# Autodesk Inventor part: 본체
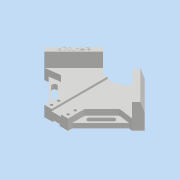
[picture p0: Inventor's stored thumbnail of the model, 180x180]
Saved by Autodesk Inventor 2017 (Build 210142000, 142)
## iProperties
Part Number: 본체
Material: 일반
Document SubType Name: Modeling
Designer: mrc
Density: 1 g/cm^3
Appearance: 기본값
Mass: 211.713 g
Surface Area: 407.173 cm^2
Volume: 211.713 cm^3
Author: mrc
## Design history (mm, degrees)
node "스케치1"
sketch "스케치2"
  geometry: L1 (0, 0)-(0, 3.931); L2 (20, -64.853)-(84.853, 0); L3 (84.853, 0)-(0, 84.853); L4 (0, 84.853)-(-84.853, 0); L5 (-84.853, 0)-(-20, -64.853); L6 (84.853, 0)-(-84.853, 0); L7 (0, -64.853)-(-20, -64.853); L8 (0, -64.853)-(20, -64.853); L9 (0, 84.853)-(35.355, 49.497); L10 (0, 84.853)-(-35.355, 49.497); L11 (24.749, 38.891)-(74.246, -10.607); L12 (-35.355, 49.497)-(-16.005, 30.147); L13 (35.355, 49.497)-(16.005, 30.147); L14 (-24.749, 38.891)-(-74.246, -10.607); L15 (0, -64.853)-(0, 30.147); L16 (0, 30.147)-(-16.005, 30.147); L17 (0, 30.147)-(16.005, 30.147); L18 (-20, -36.569)-(-49.497, -7.071); L19 (-84.853, 0)-(-63.64, -21.213); L20 (-74.246, -10.607)-(-49.497, -7.071); L21 (84.853, 0)-(63.64, -21.213); L22 (74.246, -10.607)-(49.497, -7.071); L23 (49.497, -7.071)-(20, -36.569); L24 (-20, -64.853)-(-20, -36.569); L25 (20, -64.853)-(20, -36.569); 4 further points
  constraints: 50 end point, 11 point on line, 3 perpendicular, 3 vertical, 2 horizontal, 2 midpoint, 2 parallel
  dimensions: "d10" = 120 distance of L3.end L2.end; "d13" = 20 distance of L7.start L5.end; "d14" = 20 distance of L7.start L2.start; "d15" = 50 distance of L3.end L9.end; "d16" = 50 distance of L3.end L10.end; "d17" = 15 distance between parallel lines of L3 L11; "d19" = 15 distance between parallel lines of L14 L4; "d21" = 20 distance between parallel lines of L5 L18; "d22" = 30 distance of L4.end L19.end; "d24" = 30 distance of L2.end L21.end; "d101" = 95 distance of L7.start L15.end
extrude "돌출1" new body sketch "스케치2" distance "d25" = 18; taper "d26" = 0 deg
sketch "스케치4"
  geometry: L1 (84.853, 0)-(-84.853, 0); L2 (-49.497, -7.071)-(-74.246, -10.607) reference; L3 (-24.749, 38.891)-(-16.005, 30.147) reference; L4 (-74.246, -10.607)-(-24.749, 38.891); L5 (-24.749, 38.891)-(-35.355, 49.497); L6 (24.749, 38.891)-(74.246, -10.607) reference; L7 (24.749, 38.891)-(35.355, 49.497); L8 (24.749, 38.891)-(74.246, -10.607); L9 (-35.355, 49.497)-(-84.853, 0); L10 (-84.853, 0)-(-74.246, -10.607); L11 (35.355, 49.497)-(84.853, 0); L12 (84.853, 0)-(74.246, -10.607); 2 further points
  constraints: 18 end point, 3 perpendicular, 2 midpoint
  dimensions: "d31" = 70 distance of L7.end L1.start
extrude "돌출2" join sketch "스케치4" distance "d32" = 42; taper "d33" = 0 deg
sketch "스케치5"
  geometry: L1 (0, -84.853)-(84.853, 0); L2 (84.853, 0)-(77.782, 0); L3 (-81.317, 3.536)-(-84.853, 0); L4 (84.853, 0)-(81.317, 3.536); L5 (-49.497, -7.071)-(-74.246, -10.607) reference; L6 (-68.059, -9.723)-(-49.497, -7.071); L7 (20, -36.569)-(20, -64.853) reference; L8 (20, -64.853)-(-20, -64.853) reference; L9 (-20, -64.853)-(-20, -36.569) reference; L10 (-20, -36.569)-(-49.497, -7.071) reference; L11 (-49.497, -7.071)-(-74.246, -10.607) reference; L12 (-74.246, -10.607)-(-84.853, 0) reference; L13 (-84.853, 0)-(-35.355, 49.497) reference; L14 (-35.355, 49.497)-(-16.005, 30.147) reference; L15 (-16.005, 30.147)-(16.005, 30.147) reference; L16 (16.005, 30.147)-(35.355, 49.497) reference; L17 (35.355, 49.497)-(84.853, 0) reference; L18 (84.853, 0)-(74.246, -10.607) reference; L19 (74.246, -10.607)-(49.497, -7.071) reference; L20 (49.497, -7.071)-(20, -36.569) reference; L21 (-20, -36.569)-(-49.497, -7.071) reference; L22 (-49.497, -7.071)-(-20, -36.569); L23 (-20, -64.853)-(-20, -36.569) reference; L24 (-20, -36.569)-(-20, -59.093); L25 (20, -36.569)-(20, -64.853) reference; L26 (20, -58.469)-(20, -36.569); L27 (74.246, -10.607)-(49.497, -7.071) reference; L28 (20, -36.569)-(49.497, -7.071); L29 (49.497, -7.071)-(74.246, -10.607); L30 (-84.853, 0)-(-74.246, -10.607); L31 (-20, -64.853)-(0, -84.853); L32 (0, -77.782)-(-12.929, -64.853); L33 (-20, -57.782)-(-68.059, -9.723); L34 (68.059, -9.723)-(20, -57.782); L35 (12.929, -64.853)-(0, -77.782); 2 further points
  constraints: 34 end point, 11 point on line, 4 collinear, 3 parallel, 1 perpendicular, 1 vertical alignment
extrude "돌출3" join sketch "스케치5" distance "d37" = 8; taper "d38" = 0 deg
sketch "스케치6"
  geometry: L1 (16.005, 30.147)-(-16.005, 30.147) reference; L2 (0, 30.147)-(0, -64.853); L3 (-20, -64.853)-(20, -64.853) reference; L4 (-8, 30.147)-(-8, -66.066); L5 (8, 30.147)-(8, -66.066); L6 (8, 30.147)-(-8, 30.147); L7 (-8, -66.066)-(8, -66.066); 1 further point
  constraints: 10 end point, 2 midpoint, 2 parallel, 1 collinear, 1 horizontal
  dimensions: "d39" = 8 distance between parallel lines of L2 L4; "d40" = 8 distance between parallel lines of L2 L5
extrude "돌출4" cut sketch "스케치6" distance "d41" = 3.5; taper "d42" = 0 deg
sketch "스케치7"
  geometry: L1 (20, -64.853)-(-20, -64.853) reference; L2 (0, -64.853)-(0, 30.147); L3 (-16.005, 30.147)-(16.005, 30.147) reference; L4 (6, -66.066)-(6, 30.147); L5 (-6, -66.066)-(-6, 30.147); L6 (-6, 30.147)-(6, 30.147); L7 (6, -66.066)-(-6, -66.066); 1 further point
  constraints: 10 end point, 3 parallel, 2 midpoint, 1 collinear
  dimensions: "d43" = 6 distance between parallel lines of L2 L4; "d44" = 6 distance between parallel lines of L2 L5
extrude "돌출5" cut sketch "스케치7" distance "d45" = 3; taper "d46" = 0 deg
sketch "스케치8"
  geometry: L1 (-20, -36.569)-(-20, -64.853) reference; L2 (-20, -64.853)-(-6, -64.853) reference; L3 (20, -64.853)-(20, -36.569) reference; L4 (8, -64.853)-(20, -64.853) reference; C1 r 2.25 at (14, -46.853); C2 r 2.25 at (14, -58.853); C3 r 2.25 at (-14, -46.853); C4 r 2.25 at (-14, -58.853); 1 further point
  constraints: 4 centre point
  dimensions: "d47" = 4.5 diameter of C1; "d48" = 4.5 diameter of C2; "d49" = 4.5 diameter of C3; "d50" = 4.5 diameter of C4; "d51" = 6 distance from line of L1 C4.centre; "d52" = 6 distance from line of L1 C3.centre; "d53" = 6 distance from line of L2 C4.centre; "d54" = 12 distance of C4.centre C3.centre; "d55" = 6 distance from line of L3 C1.centre; "d56" = 6 distance from line of L3 C2.centre; "d57" = 12 distance of C1.centre C2.centre; "d58" = 6 distance from line of L4 C2.centre
extrude "돌출6" cut sketch "스케치8" distance "d59" = 8; taper "d60" = 0 deg
sketch "스케치9"
  geometry: C1 r 2.25 at (14, -58.853) reference; C2 r 4 at (14, -58.853); C3 r 2.25 at (14, -46.853) reference; C4 r 4 at (14, -46.853); C5 r 2.25 at (-14, -58.853) reference; C6 r 4 at (-14, -58.853); C7 r 2.25 at (-14, -46.853) reference; C8 r 4 at (-14, -46.853); 1 further point
  constraints: 4 centre point, 4 coincident
  dimensions: "d61" = 8 diameter of C2; "d62" = 8 diameter of C4; "d63" = 8 diameter of C6; "d64" = 8 diameter of C8
extrude "돌출7" cut sketch "스케치9" distance "d65" = 10; taper "d66" = 0 deg
sketch "스케치10"
  geometry: L1 (0, 0)-(-5, 0); L2 (-15, 0)-(0, 0) reference; L3 (0, 0)-(0, 15); L4 (0, 15)-(-5, 0); 1 further point
  constraints: 6 end point, 1 point on line, 1 vertical
  dimensions: "d67" = 5 distance of L1.start L1.end; "d68" = 15 distance of L1.start L3.end
extrude "돌출8" cut sketch "스케치10" stored distance "d69" = 10; taper "d70" = 0 deg
sketch "스케치11"
  geometry: L1 (0, 0)-(0, 42) reference; L2 (0, 42)-(-5, 42); L3 (0, 42)-(-15, 42) reference; L4 (0, 42)-(0, 27); L5 (0, 27)-(-5, 42); 1 further point
  constraints: 6 end point, 2 point on line
  dimensions: "d71" = 5 distance of L1.end L2.end; "d72" = 15 distance of L1.end L4.end
extrude "돌출9" cut sketch "스케치11" stored distance "d73" = 10; taper "d74" = 0 deg
sketch "스케치14"
  geometry: L1 (-24.749, 38.891)-(-31.82, 45.962) reference; L2 (31.82, 45.962)-(81.317, -3.536) reference; L3 (81.317, -3.536)-(74.246, -10.607) reference; L4 (74.246, -10.607)-(24.749, 38.891) reference; L5 (24.749, 38.891)-(31.82, 45.962) reference; L6 (-81.317, -3.536)-(-31.82, 45.962) reference; L7 (-31.82, 45.962)-(-24.749, 38.891) reference; L8 (-24.749, 38.891)-(-74.246, -10.607) reference; L9 (-74.246, -10.607)-(-81.317, -3.536) reference; 2 further points
  constraints: 1 other
  dimensions: "d102" = 35 distance from line of point (-53.033, 17.678) L1; "d103" = 5 distance from line of point (-53.033, 17.678) L8
  node "절단 모서리 투영2"
sketch "스케치16"
  geometry: L1 (-74.246, -10.607)-(-84.853, 0) reference; L2 (-52.326, -21.213)-(-46.669, -15.556); L3 (-84.853, 0)-(-76.368, 8.485); L4 (-84.853, 0)-(-35.355, 49.497) reference; L5 (-52.326, -15.556)-(-26.877, -41.006); L6 (-20, -36.569)-(-20, -57.782) reference; L7 (-32.534, -41.006)-(-26.877, -35.349); L8 (-32.534, -41.006)-(-52.326, -21.213); L9 (-76.368, 2.828)-(-82.024, -2.828); L10 (-76.368, 14.142)-(-87.681, 2.828); L11 (-73.539, 11.314)-(-76.368, 14.142); L12 (-17.172, -45.054)-(-20, -42.225); L13 (-26.877, -35.349)-(-46.669, -15.556); A1 r 4 centre (-49.497, -18.385) between (-52.326, -15.556) and (-52.326, -21.213); 2 further points
  constraints: 20 end point, 6 perpendicular, 4 point on line, 2 midpoint, 2 point on circle, 1 centre point, 3 other
  dimensions: "d81" = 12 distance of L1.end L3.end; "d83" = 8 diameter of A1; "d85" = 4 distance between parallel lines of L5 L8
extrude "돌출10" cut sketch "스케치16" stored distance "d87" = 10; taper "d88" = 0 deg
sketch "스케치17"
  geometry: L1 (20, -57.782)-(20, -36.569) reference; L2 (84.853, 0)-(74.246, -10.607) reference; L3 (52.326, -15.556)-(35.355, -32.527); L4 (29.698, -38.184)-(35.355, -32.527); L5 (26.87, -35.355)-(32.527, -29.698); L6 (32.527, -41.012)-(38.184, -35.355); L7 (38.184, -35.355)-(52.326, -21.213); L8 (76.368, 2.828)-(82.024, -2.828); L9 (32.527, -29.698)-(46.669, -15.556); A1 r 4 centre (49.497, -18.385) between (52.326, -21.213) and (46.669, -15.556); A2 r 4 centre (29.698, -38.184) between (26.87, -35.355) and (32.527, -41.012); 1 further point
  constraints: 14 end point, 5 point on circle, 2 centre point, 1 coincident, 1 perpendicular
  dimensions: "d93" = 8 diameter of A1; "d94" = 8 diameter of A2; "d96" = 4 distance between parallel lines of L3 L7
extrude "돌출11" cut sketch "스케치17" stored distance "d97" = 10; taper "d98" = 0 deg
fillet "모깎기1" dims "d99" = 5
fillet "모깎기2" dims "d100" = 5
feature "엠보싱1" dims "d10" = 120, "d13" = 20, "d14" = 20, "d15" = 50, "d16" = 50, "d17" = 15, "d19" = 15, "d21" = 20, "d22" = 30, "d24" = 30, "d26" = 0, "d101" = 95, "d104" = 0.5, "d105" = 0
node "솔리드1"
node "절단 모서리 투영1"
other parameters: "d18" = 15, "d36" = 5, "d86" = 4, "d95" = 4
